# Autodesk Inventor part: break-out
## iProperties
Shininess: 64.0
Length Units: 11272
Angle Units: 11279
Time Units: 11290
Mass Units: 11286
Length Display Precision: 3
Angle Display Precision: 2
Compacted: True
Part Number: break-out
Document SubType Name: Modeling
Created: 2002-11
Designer: Elise Moss
Density: 0.0
Volumn: 0.0
Area: 0.0
PropertySet Name: Model Information
Control State: 0
Master: False
Checked Out: False
Author: Elise Moss
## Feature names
1. Extrusion1
2. Shell1
3. Extrusion2
